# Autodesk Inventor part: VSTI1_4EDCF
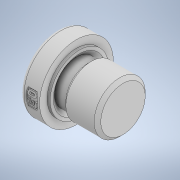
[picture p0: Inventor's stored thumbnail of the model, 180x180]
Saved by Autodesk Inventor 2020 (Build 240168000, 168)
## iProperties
Created: 2019-12
Part Number: VSTI1_4EDCF
Material: Generico
Description: STEP AP203
Document SubType Name: Modeling
Designer: carlo
Density: 1 g/cm^3
Appearance: Default
DataBaseUnit: MM
Title: p:/temp/worker_146/temp/exporttempdir_1896_249_xOmRy/format_0/EO Verschluss-Stopfen fuer Einschraubloecher VSTI1_4EDCF.stp
Revision Number: NONE
Sending System: PARTsolutions
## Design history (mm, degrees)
feature "_EO Verschluss-Stopfen fuer Einschraubloecher VSTI1_4EDCF"
node "Piano di lavoro1"
node "Piano di lavoro2"
node "Asse di lavoro1"
node "Solido1"
other parameters: "d0" = 0, "d1" = 0
